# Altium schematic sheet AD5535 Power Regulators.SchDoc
size A
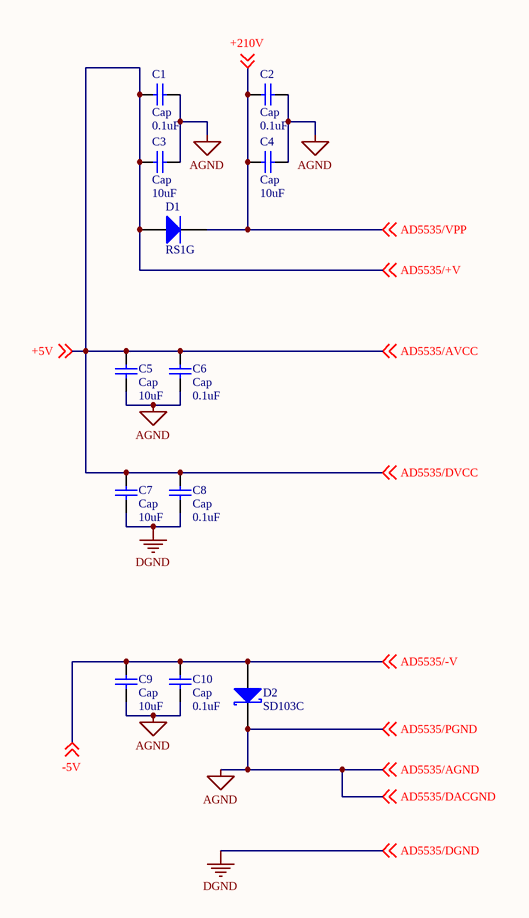
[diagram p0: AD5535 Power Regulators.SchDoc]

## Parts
C1  Cap  value 0.1uF  [C1206]
C2  Cap  value 0.1uF  [C1206]
C3  Cap  value 10uF  [C1206]
C4  Cap  value 10uF  [PCBComponent_1 - duplicate]
C5  Cap  value 10uF  [C1206]
C6  Cap  value 0.1uF  [C1206]
C7  Cap  value 10uF  [C1206]
C8  Cap  value 0.1uF  [C1206]
C9  Cap  value 10uF  [C1206]
C10  Cap  value 0.1uF  [C1206]
D1  RS1G  [SMB]
D2  SD103C  [425]

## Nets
AGND: C1.2 C2.2 C3.2 C4.2 C5.1 C6.1 C9.1 C10.1 D2.2(K) ; off-sheet AD5535/PGND, off-sheet AD5535/AGND, off-sheet AD5535/DACGND  [also labelled AD5535/AGND, AD5535/DACGND, AD5535/PGND]
DGND: C7.1 C8.1 ; off-sheet AD5535/DGND  [also labelled AD5535/DGND]
+5V: C1.1 C3.1 C5.2 C6.2 C7.2 C8.2 D1.1(A) ; off-sheet +5V, off-sheet AD5535/+V, off-sheet AD5535/AVCC, off-sheet AD5535/DVCC  [also labelled AD5535/+V, AD5535/AVCC, AD5535/DVCC]
+210V: C2.1 C4.1 D1.2(K) ; off-sheet AD5535/VPP, off-sheet +210V  [also labelled AD5535/VPP]
-5V: C9.2 C10.2 D2.1(A) ; off-sheet AD5535/-V, off-sheet -5V  [also labelled AD5535/-V]

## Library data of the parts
C1-C10 = Cap: Capacitor
D1 = Diode: Default Diode
D2 = D Schottky: Schottky Diode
